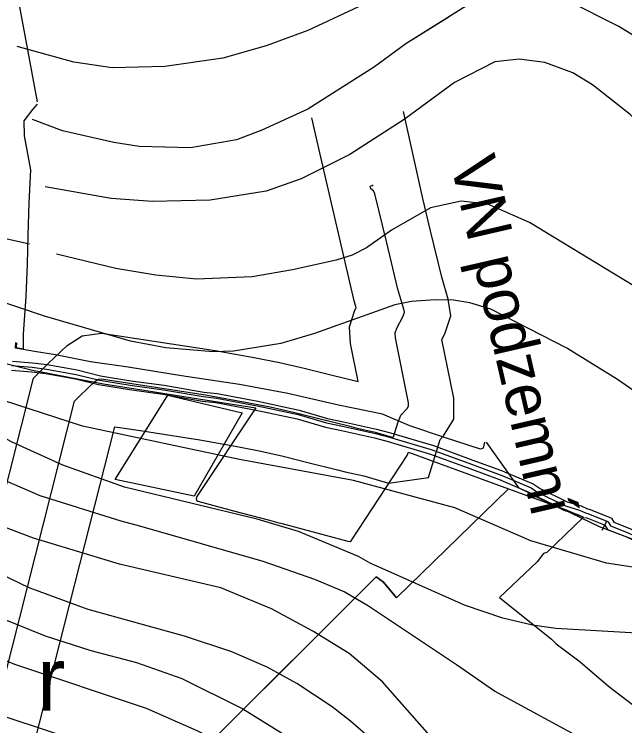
# Model space of a CAD drawing. Extents: x -1900516 to -575031, y -3809306 to -1157387.
# Drawn here: x -578675.6 to -578473.4, y -1159083.3 to -1158847.7 of the extents above; entities that cross this region are included whole.
import ezdxf

# ---------------------------------------------------------------- set-up
doc = ezdxf.new("R2010")
doc.units = 0
for name, color, linetype in [('01_OBVOD NEŘEŠENÉ', 7, 'Continuous'), ('01_OBVOD PÚ', 7, 'Continuous'), ('01_VRSTEVNICE', 7, 'Continuous'), ('01_ZASTAV_PLOCHY', 7, 'Continuous'), ('02_KULTURY STAV', 7, 'Continuous'), ('07_ELEKTRO', 7, 'Continuous'), ('07_OCH_P A POPISY TI', 7, 'Continuous'), ('07_SDĚLOVACÍ', 7, 'Continuous')]:
    doc.layers.add(name, color=color, linetype=linetype)

msp = doc.modelspace()

# ---------------------------------------------------------------- linework, layer by layer
at = {"layer": '01_OBVOD NEŘEŠENÉ'}
for p, q in [((-578549.02, -1159040.97), (-578511.91, -1159004.91)), ((-578549.02, -1159040.97), (-578511.91, -1159004.91)), ((-578511.91, -1159004.91), (-578549.02, -1159040.97)), ((-578511.91, -1159004.91), (-578493.31, -1159011.59)), ((-578511.91, -1159004.91), (-578493.31, -1159011.59)), ((-578493.31, -1159011.59), (-578487.06, -1159014.19)), ((-578493.31, -1159011.59), (-578487.06, -1159014.19)), ((-578487.06, -1159014.19), (-578499.19, -1159025.95)), ((-578487.06, -1159014.19), (-578499.19, -1159025.95)), ((-578500.31, -1159026.31), (-578502.35, -1159028.99)), ((-578500.31, -1159026.31), (-578502.35, -1159028.99)), ((-578499.19, -1159025.95), (-578500.31, -1159026.31)), ((-578499.19, -1159025.95), (-578500.31, -1159026.31)), ((-578502.35, -1159028.99), (-578514.88, -1159040.83)), ((-578502.35, -1159028.99), (-578514.88, -1159040.83)), ((-578611.17, -1159089.26), (-578555.67, -1159033.98)), ((-578611.17, -1159089.26), (-578555.67, -1159033.98)), ((-578555.67, -1159033.98), (-578611.17, -1159089.26)), ((-578555.67, -1159033.98), (-578553.24, -1159035.74)), ((-578555.67, -1159033.98), (-578553.24, -1159035.74)), ((-578553.24, -1159035.74), (-578555.67, -1159033.98)), ((-578553.24, -1159035.74), (-578549.02, -1159040.97)), ((-578553.24, -1159035.74), (-578549.02, -1159040.97)), ((-578549.02, -1159040.97), (-578553.24, -1159035.74)), ((-578514.88, -1159040.83), (-578497.68, -1159054.64)), ((-578514.88, -1159040.83), (-578497.68, -1159054.64)), ((-578497.68, -1159054.64), (-578496.06, -1159056.23)), ((-578497.68, -1159054.64), (-578496.06, -1159056.23)), ((-578496.06, -1159056.23), (-578488.14, -1159062.18)), ((-578496.06, -1159056.23), (-578488.14, -1159062.18)), ((-578488.14, -1159062.18), (-578478.75, -1159070.26)), ((-578488.14, -1159062.18), (-578478.75, -1159070.26)), ((-578478.75, -1159070.26), (-578470.8, -1159076.31)), ((-578478.75, -1159070.26), (-578470.8, -1159076.31))]:
    msp.add_line(p, q, dxfattribs=at)
at = {"layer": '01_OBVOD PÚ'}
msp.add_lwpolyline([(-578720.95, -1158952.72), (-578669.59, -1158965.57), (-578646.08, -1158970.03), (-578631.87, -1158972.26), (-578619.46, -1158974.25), (-578595.62, -1158978.07), (-578615.17, -1159007.42), (-578615.35, -1159008.18), (-578615.28, -1159008.61), (-578614.78, -1159008.95), (-578602.97, -1159012.1), (-578591.07, -1159015.27), (-578587.92, -1159016.11), (-578587.29, -1159016.28), (-578565.09, -1159022.2), (-578564.38, -1159022.29), (-578564.04, -1159022.07), (-578545.43, -1158993.79), (-578545.02, -1158992.73), (-578511.91, -1159004.91), (-578549.02, -1159040.97), (-578553.24, -1159035.74), (-578555.67, -1159033.98), (-578611.17, -1159089.26)], dxfattribs=at)
at = {"layer": '01_VRSTEVNICE'}
for points in [[(-578435.66, -1158880.07), (-578461.76, -1158860.17), (-578475.3, -1158851.71), (-578492.23, -1158843.24), (-578502.39, -1158840.14), (-578507.47, -1158839.57), (-578517.63, -1158841.41), (-578526.66, -1158845.5), (-578545.85, -1158857.49), (-578556.29, -1158865.11), (-578578.3, -1158879.08), (-578593.54, -1158886.13), (-578602.01, -1158889.24), (-578617.24, -1158891.92), (-578634.17, -1158891.49), (-578642.64, -1158890.22), (-578659.57, -1158886.27), (-578669.59, -1158882.6)], [(-578559.91, -1158844.48), (-578578.3, -1158853.12), (-578592.13, -1158858.2), (-578606.52, -1158862.29), (-578625.71, -1158864.97), (-578643.2, -1158865.39), (-578655.9, -1158863.56), (-578674.67, -1158858.34)], [(-578531.86, -1158848.75), (-578545.85, -1158857.49), (-578556.29, -1158865.11), (-578578.3, -1158879.08), (-578593.54, -1158886.13), (-578602.01, -1158889.24), (-578617.24, -1158891.92), (-578634.17, -1158891.49), (-578642.64, -1158890.22), (-578659.57, -1158886.27), (-578669.59, -1158882.6)], [(-578531.86, -1158848.75), (-578545.85, -1158857.49), (-578556.29, -1158865.11), (-578578.3, -1158879.08), (-578593.54, -1158886.13), (-578602.01, -1158889.24), (-578617.24, -1158891.92), (-578634.17, -1158891.49), (-578642.64, -1158890.22), (-578659.57, -1158886.27), (-578669.59, -1158882.6)], [(-578436.64, -1158912.59), (-578462.75, -1158890.08), (-578471.61, -1158880.87), (-578484.05, -1158871.03), (-578490.54, -1158867.08), (-578499.85, -1158863.7), (-578508.32, -1158862.57), (-578516.36, -1158863.42), (-578529.77, -1158870.33), (-578546.42, -1158882.6), (-578564.47, -1158894.18), (-578580.56, -1158902.22), (-578592.13, -1158906.31), (-578610.75, -1158909.27), (-578629.94, -1158909.7), (-578643.49, -1158908.71), (-578665.36, -1158904.9)], [(-578436.64, -1158912.59), (-578462.75, -1158890.08), (-578471.61, -1158880.87), (-578484.05, -1158871.03), (-578490.54, -1158867.08), (-578499.85, -1158863.7), (-578508.32, -1158862.57), (-578516.36, -1158863.42), (-578529.77, -1158870.33), (-578546.42, -1158882.6), (-578564.47, -1158894.18), (-578580.56, -1158902.22), (-578592.13, -1158906.31), (-578610.75, -1158909.27), (-578629.94, -1158909.7), (-578643.49, -1158908.71), (-578665.36, -1158904.9)], [(-578670.51, -1158923.78), (-578683.51, -1158920.99), (-578698.33, -1158920.29), (-578713.99, -1158922.1), (-578746.71, -1158929.52), (-578760.14, -1158931.47), (-578778.59, -1158932.45), (-578795.09, -1158931.33), (-578804.88, -1158929.66), (-578814.39, -1158926.86), (-578832.84, -1158919.59), (-578850.46, -1158909.66), (-578866.12, -1158897.92)], [(-578466.43, -1158940.03), (-578477.28, -1158933.4), (-578504.93, -1158916.61), (-578518.76, -1158910.54), (-578527.51, -1158909.55), (-578537.67, -1158911.81), (-578550.65, -1158919.15), (-578558.96, -1158925.03), (-578563.62, -1158927.44), (-578568.99, -1158929.17)], [(-578466.43, -1158940.03), (-578477.28, -1158933.4), (-578504.93, -1158916.61), (-578518.76, -1158910.54), (-578527.51, -1158909.55), (-578537.67, -1158911.81), (-578550.65, -1158919.15), (-578558.96, -1158925.03), (-578563.62, -1158927.44), (-578568.99, -1158929.17)], [(-578568.99, -1158929.17), (-578583.4, -1158932.31), (-578596.83, -1158934.69), (-578615.28, -1158935.39), (-578628.7, -1158934.13), (-578641.99, -1158931.89), (-578661.56, -1158927.14)], [(-578452.25, -1158985.02), (-578475.74, -1158968.67), (-578492.52, -1158958.32), (-578517.69, -1158945.31), (-578524.68, -1158943.22), (-578530.1, -1158942.34), (-578536.14, -1158942.24), (-578543.97, -1158942.8), (-578549.57, -1158943.92), (-578576.13, -1158953.43), (-578587.32, -1158956.78), (-578602.98, -1158959.3), (-578609.69, -1158959.44), (-578625.35, -1158958.18), (-578637.09, -1158955.94), (-578665.62, -1158947.69), (-578684.07, -1158941.54), (-578694.14, -1158939.58), (-578703.37, -1158939.02), (-578716.79, -1158940.14), (-578727.9, -1158940.22), (-578769.64, -1158937.35), (-578801.8, -1158937.21), (-578815.92, -1158936.37)], [(-578459.8, -1159053.26), (-578496.15, -1159051.16), (-578503.98, -1159050.04), (-578513.77, -1159047.66), (-578526.49, -1159043.33), (-578557.68, -1159029.49), (-578561.59, -1159027.25), (-578581.45, -1159019), (-578595.15, -1159014.95), (-578639.05, -1159004.32), (-578659.46, -1158997.05), (-578676.24, -1158989.36), (-578706.72, -1158973.28), (-578716.51, -1158969.51), (-578722.38, -1158967.97), (-578734.69, -1158966.57), (-578747.83, -1158966.43), (-578779.15, -1158967.55), (-578839.83, -1158971.88), (-578861.23, -1158971.04)], [(-578307.18, -1159026.06), (-578311.17, -1159029.35), (-578331.03, -1159046.27), (-578337.6, -1159041.79), (-578352.98, -1159051.3), (-578368.69, -1159063.94), (-578372.55, -1159065), (-578385.7, -1159065.56), (-578394.08, -1159064.02), (-578399.82, -1159061.51), (-578404.85, -1159057.87), (-578416.6, -1159045.43), (-578420.65, -1159042.07), (-578429.04, -1159038.3), (-578437.43, -1159035.92), (-578479.38, -1159029.49), (-578504.54, -1159022.08), (-578529.71, -1159011.17), (-578563.27, -1159002.08), (-578601.02, -1158995.09), (-578653.03, -1158984.05), (-578688.13, -1158972.72), (-578690.07, -1158972.06)], [(-578472.66, -1159094.08), (-578484.41, -1159089.33), (-578516.57, -1159071.85), (-578529.15, -1159063.18), (-578558.23, -1159043.75), (-578566.28, -1159039), (-578576.08, -1159034.88), (-578593.19, -1159028.93), (-578634.02, -1159017.18), (-578640.17, -1159015.51), (-578667.02, -1159007.12), (-578682.12, -1159000.69), (-578695.54, -1158993.97), (-578712.32, -1158984.47), (-578723.5, -1158980.27), (-578729.1, -1158979.15), (-578740.3, -1158978.71), (-578752.03, -1158979.01), (-578781.95, -1158982.51), (-578814.67, -1158988.24), (-578828.65, -1158989.64), (-578839.14, -1158989.5)], [(-578534.74, -1159090.17), (-578553.62, -1159068.78), (-578564.67, -1159059.41), (-578576.69, -1159051.95), (-578590.39, -1159044.59), (-578607.17, -1159037.6), (-578640.73, -1159029.77), (-578669.25, -1159021.24), (-578689.39, -1159013.55), (-578704.49, -1159005.44), (-578725.18, -1158995.65), (-578730.77, -1158993.83), (-578743.22, -1158991.88), (-578750.71, -1158991.65), (-578759.86, -1158992.16), (-578778.31, -1158995.09), (-578821.38, -1159004.88), (-578832, -1159005.86), (-578839.25, -1159005.86), (-578846.27, -1159005.02), (-578858.15, -1159001.8)], [(-578551.52, -1159092.83), (-578564.25, -1159081.78), (-578570.26, -1159077.03), (-578582, -1159069.34), (-578591.79, -1159063.88), (-578603.54, -1159058.85), (-578619.2, -1159053.68), (-578651.08, -1159044.87), (-578670.65, -1159037.6), (-578686.31, -1159030.19), (-578715.67, -1159014.25), (-578731.19, -1159008.65), (-578744.2, -1159006.84), (-578757.49, -1159006.8), (-578769.64, -1159007.54), (-578787.26, -1159010.33), (-578818.58, -1159018.44), (-578834.24, -1159020.26), (-578842.09, -1159020.22), (-578851.86, -1159019.14), (-578867.33, -1159015.22)], [(-578861.35, -1159036.15), (-578847.38, -1159036.76), (-578837.88, -1159035.92), (-578802.92, -1159026.97), (-578762.65, -1159019.14), (-578752.59, -1159019.14), (-578737.48, -1159022.36), (-578727.42, -1159025.71), (-578680.44, -1159047.52), (-578665.34, -1159053.54), (-578650.24, -1159058.43), (-578635.14, -1159062.34), (-578620.04, -1159067.66), (-578599.9, -1159077.73), (-578584.8, -1159087.09), (-578569.28, -1159099.26), (-578523.56, -1159144.98), (-578512.23, -1159154.49), (-578505.38, -1159158.4), (-578500.35, -1159160.5), (-578465.11, -1159170.57)], [(-578472.39, -1159185.53), (-578482.45, -1159182.03), (-578499.23, -1159173.92), (-578509.16, -1159168.33), (-578525.8, -1159156.17), (-578557.82, -1159123.73), (-578564.53, -1159117.72), (-578580.05, -1159105.55), (-578596.55, -1159094.5), (-578615, -1159085), (-578631.78, -1159077.59), (-578675.41, -1159063.04), (-578727.7, -1159041.65), (-578751.47, -1159034.38), (-578763.49, -1159032.7), (-578767.9, -1159032.53), (-578773.84, -1159033.12), (-578793.97, -1159037.32), (-578827.53, -1159047.8), (-578844.31, -1159051.58), (-578858.43, -1159052.7)], [(-578471.83, -1159210.28), (-578500.63, -1159192.94), (-578526.49, -1159173.36), (-578537.54, -1159164), (-578566.07, -1159134.07), (-578581.45, -1159122.19), (-578602.14, -1159109.47), (-578615.56, -1159102.89), (-578634.02, -1159095.2), (-578684.35, -1159078.43), (-578701.69, -1159071.99), (-578729.38, -1159064.3), (-578745.04, -1159062.62), (-578757.48, -1159062.77)]]:
    msp.add_lwpolyline(points, dxfattribs=at)
at = {"layer": '01_ZASTAV_PLOCHY'}
msp.add_lwpolyline([(-578615.95, -1159007.32), (-578642.16, -1159001.8), (-578624.73, -1158973.84), (-578600.14, -1158979.66)], close=True, dxfattribs=at)
at = {"layer": '02_KULTURY STAV'}
for points in [[(-578720.95, -1158952.72), (-578669.59, -1158965.57), (-578646.08, -1158970.03), (-578631.87, -1158972.26), (-578619.46, -1158974.25), (-578595.62, -1158978.07), (-578615.17, -1159007.42), (-578615.35, -1159008.18), (-578615.28, -1159008.61), (-578614.78, -1159008.95), (-578602.97, -1159012.1), (-578591.07, -1159015.27), (-578587.92, -1159016.11), (-578587.29, -1159016.28), (-578565.09, -1159022.2), (-578564.38, -1159022.29), (-578564.04, -1159022.07), (-578545.43, -1158993.79), (-578545.02, -1158992.73), (-578511.91, -1159004.91), (-578549.02, -1159040.97), (-578553.24, -1159035.74), (-578555.67, -1159033.98), (-578573.55, -1159051.8), (-578573.95, -1159052.2), (-578574.68, -1159052.93), (-578611.17, -1159089.26)], [(-578611.17, -1159089.26), (-578574.68, -1159052.93), (-578573.95, -1159052.2), (-578573.55, -1159051.8), (-578555.67, -1159033.98), (-578553.24, -1159035.74), (-578549.02, -1159040.97), (-578511.91, -1159004.91), (-578493.31, -1159011.59), (-578487.06, -1159014.19), (-578499.19, -1159025.95), (-578500.31, -1159026.31), (-578502.35, -1159028.99), (-578514.88, -1159040.83), (-578497.68, -1159054.64), (-578496.06, -1159056.23), (-578488.14, -1159062.18), (-578478.75, -1159070.26), (-578470.8, -1159076.31)]]:
    msp.add_lwpolyline(points, dxfattribs=at)
at = {"layer": '07_ELEKTRO'}
for points in [[(-578667.85, -1158876.74), (-578678.68, -1158818.41)], [(-578674.85, -1158956.46), (-578674.95, -1158958.08), (-578672.53, -1158958.53), (-578672.5, -1158953.65), (-578671.66, -1158941.21), (-578671.2, -1158930.44), (-578670.99, -1158920.92), (-578670.64, -1158910.18), (-578670.16, -1158899.18), (-578672.23, -1158887.96), (-578672.29, -1158883.04), (-578669.45, -1158879.2), (-578667.88, -1158877.51)], [(-578655.63, -1158975.82), (-578654.43, -1158974.59), (-578653.9, -1158974.04), (-578648.75, -1158969.25), (-578647.69, -1158968.55), (-578646.83, -1158968.43), (-578632.31, -1158970.63), (-578611.58, -1158973.85), (-578598.4, -1158976.25), (-578590.83, -1158977.75), (-578583.06, -1158979.48), (-578574.75, -1158981.57), (-578564.72, -1158984.03), (-578562.45, -1158984.65), (-578556.03, -1158986.06), (-578550.45, -1158987.72), (-578549.96, -1158987.65), (-578548.47, -1158982.67), (-578547.92, -1158981.29), (-578547.5, -1158980.48), (-578545.5, -1158978.23), (-578545.01, -1158977.45), (-578545.01, -1158976.33), (-578549.34, -1158954.85), (-578549.43, -1158953.25), (-578548.89, -1158951.61), (-578546.8, -1158947.64), (-578546.37, -1158946.33), (-578546.52, -1158945.34), (-578548.49, -1158938.7), (-578552.33, -1158922.9), (-578556.11, -1158907.18), (-578556.6, -1158906.2), (-578557.51, -1158905.47), (-578557.72, -1158904.62), (-578557.01, -1158904.41), (-578556.7, -1158904.22)], [(-578519.83, -1158989.42), (-578520.27, -1158991.37), (-578521.13, -1158991.67), (-578533.03, -1158987.84), (-578544.52, -1158983.94), (-578553.66, -1158980.17), (-578568.21, -1158977.17), (-578584.99, -1158973.27), (-578600.98, -1158970.28), (-578620.19, -1158967.42), (-578637.84, -1158964.59), (-578650.31, -1158962.76), (-578661.94, -1158960.43), (-578668.92, -1158959.35), (-578675.14, -1158958.27), (-578675.04, -1158956.45)], [(-578686.82, -1159098.53), (-578655.63, -1158975.82)], [(-578375.49, -1159242.09), (-578380.42, -1159216.12), (-578381.93, -1159203.88), (-578382.54, -1159199.73), (-578384.55, -1159186.09), (-578386.38, -1159176.16), (-578390.56, -1159151.59), (-578391.21, -1159148.16), (-578394.43, -1159131.17), (-578399.69, -1159102.22), (-578404.89, -1159092.56), (-578411.88, -1159080.15), (-578418.97, -1159068.8), (-578422.18, -1159064.61), (-578431.81, -1159052.53), (-578438.08, -1159044.85), (-578448.94, -1159035.38), (-578461.15, -1159025.12), (-578481.73, -1159017.46), (-578508.31, -1159004.66), (-578519.18, -1158989.37)]]:
    msp.add_lwpolyline(points, dxfattribs=at)
at = {"layer": '07_OCH_P A POPISY TI'}
for p, q in [((-578540.31, -1158908.71), (-578546.71, -1158879.93)), ((-578537.75, -1158919.38), (-578540.31, -1158908.71)), ((-578534, -1158934.79), (-578537.75, -1158919.38)), ((-578531.84, -1158942.07), (-578534, -1158934.79)), ((-578531, -1158947.61), (-578531.84, -1158942.07)), ((-578532.94, -1158953.51), (-578531, -1158947.61)), ((-578533.93, -1158955.39), (-578532.94, -1158953.51)), ((-578530.01, -1158974.83), (-578533.93, -1158955.39)), ((-578694.97, -1159069.69), (-578669.18, -1158968.24)), ((-578530.01, -1158981.77), (-578530.01, -1158974.83)), ((-578533.46, -1158987.26), (-578530.01, -1158981.77)), ((-578670.57, -1159095.49), (-578642.31, -1158984.29)), ((-578642.31, -1158984.29), (-578634.58, -1158985.46)), ((-578634.58, -1158985.46), (-578614.08, -1158988.64)), ((-578614.08, -1158988.64), (-578601.2, -1158990.99)), ((-578538.34, -1159001.14), (-578534.56, -1158988.5)), ((-578534.56, -1158988.5), (-578533.46, -1158987.26)), ((-578601.2, -1158990.99), (-578593.92, -1158992.43)), ((-578593.92, -1158992.43), (-578586.52, -1158994.08)), ((-578586.52, -1158994.08), (-578578.37, -1158996.13)), ((-578578.37, -1158996.13), (-578568.48, -1158998.55)), ((-578568.48, -1158998.55), (-578566.04, -1158999.22)), ((-578566.04, -1158999.22), (-578559.78, -1159000.59)), ((-578559.78, -1159000.59), (-578551.58, -1159003.03)), ((-578551.58, -1159003.03), (-578538.34, -1159001.14))]:
    msp.add_line(p, q, dxfattribs=at)
for points in [[(-578669.18, -1158968.24), (-578664.39, -1158963.31), (-578658.05, -1158957.42), (-578653.12, -1158954.16), (-578646.74, -1158953.27), (-578630.04, -1158955.8), (-578609.08, -1158959.06), (-578595.6, -1158961.51), (-578587.74, -1158963.07), (-578579.6, -1158964.88), (-578571.13, -1158967.01), (-578561.72, -1158969.32), (-578564.26, -1158956.76), (-578564.57, -1158951.26), (-578562.75, -1158945.73), (-578562.3, -1158944.88), (-578562.98, -1158942.61), (-578574.4, -1158893.61), (-578577.04, -1158881.97)], [(-578676.2, -1158962.53), (-578669.53, -1158963.12), (-578664.68, -1158963.72), (-578654.73, -1158965.49), (-578647.06, -1158967.41), (-578636.94, -1158969.04), (-578625.89, -1158970.57), (-578612.78, -1158972.84), (-578608.43, -1158973.32), (-578594.87, -1158975.87), (-578581.18, -1158978.79), (-578571.81, -1158981.54), (-578566.55, -1158982.64), (-578555.58, -1158985.09), (-578550.93, -1158986.3), (-578536.75, -1158990.56), (-578523.67, -1158995.33), (-578513.27, -1158999.15)], [(-578676.53, -1158965.51), (-578669.85, -1158966.1), (-578665.13, -1158966.69), (-578655.36, -1158968.42), (-578647.66, -1158970.35), (-578637.38, -1158972), (-578626.35, -1158973.54), (-578613.2, -1158975.81), (-578608.87, -1158976.29), (-578595.46, -1158978.81), (-578581.91, -1158981.7), (-578572.54, -1158984.45), (-578567.19, -1158985.57), (-578556.28, -1158988.01), (-578551.74, -1158989.18), (-578537.69, -1158993.41), (-578524.71, -1158998.15), (-578514.3, -1159001.97)], [(-578513.19, -1158999.18), (-578503.69, -1159003.25), (-578501.39, -1159004.74), (-578492.42, -1159009.14), (-578487.8, -1159010.51), (-578485.75, -1159011.46)], [(-578514.37, -1159001.94), (-578505.1, -1159005.91), (-578502.86, -1159007.35), (-578493.51, -1159011.94), (-578488.87, -1159013.32), (-578487.01, -1159014.19)], [(-578486.08, -1159011.35), (-578485.12, -1159011.55), (-578478.77, -1159014.13)], [(-578486.67, -1159014.3), (-578485.98, -1159014.43), (-578479.91, -1159016.91)], [(-578478.72, -1159014.16), (-578477.79, -1159014.58), (-578477.04, -1159015.92), (-578471.67, -1159018.03), (-578465.94, -1159020.72), (-578460.29, -1159023.62), (-578458.85, -1159024.5)], [(-578479.96, -1159016.88), (-578479.93, -1159016.9), (-578479.14, -1159018.32), (-578472.85, -1159020.79), (-578467.26, -1159023.42), (-578461.75, -1159026.24), (-578460.41, -1159027.06)]]:
    msp.add_lwpolyline(points, dxfattribs=at)
at = {"layer": '07_SDĚLOVACÍ'}
for points in [[(-578676.37, -1158964.02), (-578669.69, -1158964.61), (-578664.91, -1158965.21), (-578655.05, -1158966.96), (-578647.36, -1158968.88), (-578637.16, -1158970.52), (-578626.12, -1158972.05), (-578612.99, -1158974.33), (-578608.65, -1158974.8), (-578595.16, -1158977.34), (-578581.55, -1158980.25), (-578572.18, -1158982.99), (-578566.87, -1158984.11), (-578555.93, -1158986.55), (-578551.34, -1158987.74), (-578537.22, -1158991.98), (-578524.19, -1158996.74), (-578513.78, -1159000.56)], [(-578513.78, -1159000.56), (-578504.4, -1159004.58), (-578502.12, -1159006.05), (-578492.96, -1159010.54), (-578488.34, -1159011.92), (-578486.38, -1159012.82)], [(-578486.38, -1159012.82), (-578485.55, -1159012.99), (-578479.34, -1159015.52)], [(-578480.83, -1159018.5), (-578479.34, -1159015.52)], [(-578479.34, -1159015.52), (-578478.86, -1159015.74), (-578478.09, -1159017.12), (-578472.26, -1159019.41), (-578466.6, -1159022.07), (-578461.02, -1159024.93), (-578459.63, -1159025.78)]]:
    msp.add_lwpolyline(points, dxfattribs=at)

# ---------------------------------------------------------------- texts
at = {"layer": '02_KULTURY STAV'}
msp.add_text('r', height=21, dxfattribs=at).set_placement((-578668.01, -1159078.29))
msp.add_text('r', height=21, dxfattribs=at).set_placement((-578668.01, -1159078.29))
at = {"layer": '07_OCH_P A POPISY TI'}
msp.add_text('VN podzemní', height=15, rotation=283.0104, dxfattribs=at).set_placement((-578531.22, -1158896.52))

doc.saveas('drawing.dxf')
